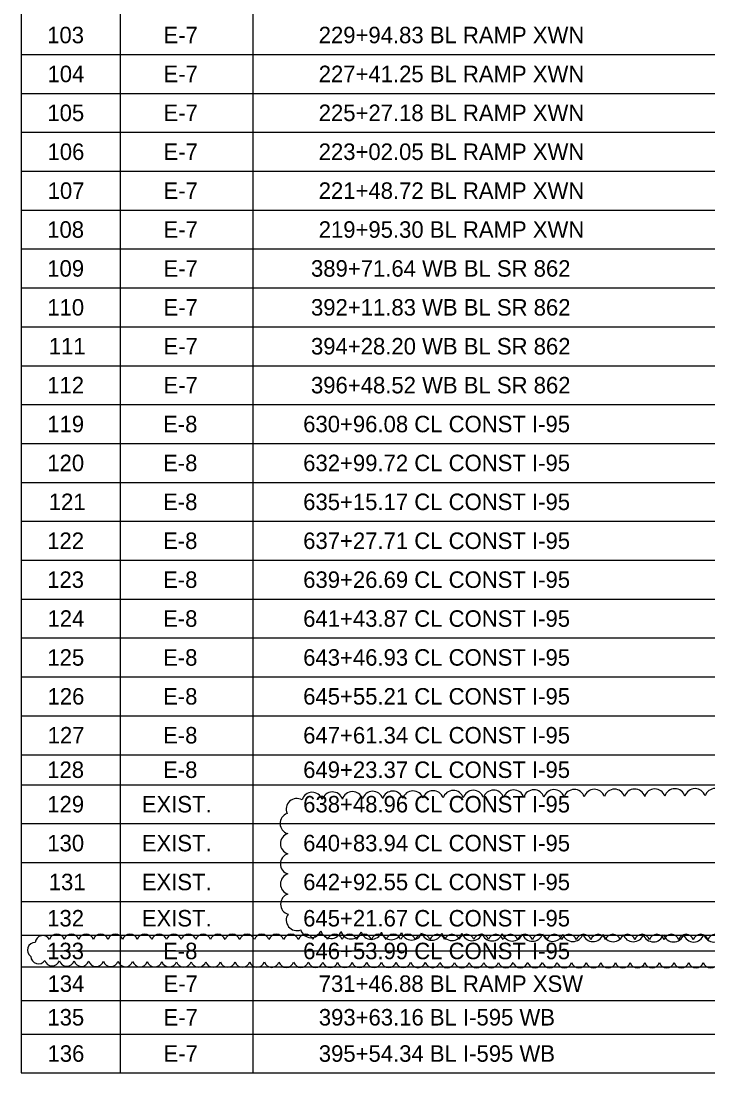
# Model space of a CAD drawing. Extents: x -818.1 to -802.4, y -2221.2 to -2187.7.
# Drawn here: x -817.208 to -814.295, y -2206.269 to -2201.807 of the extents above; entities that cross this region are included whole.
import ezdxf

# ---------------------------------------------------------------- set-up
doc = ezdxf.new("R2010")
doc.units = 0
for name, color, linetype in [('PlotBorder_dp', 7, 'Continuous'), ('SheetBorder_dp', 7, 'Continuous'), ('SheetLines_dp', 7, 'Continuous'), ('TextMinor', 7, 'Continuous'), ('TextTitle', 7, 'Continuous')]:
    doc.layers.add(name, color=color, linetype=linetype)

msp = doc.modelspace()

# ---------------------------------------------------------------- linework, layer by layer
at = {"layer": 'PlotBorder_dp'}
for p, q in [((-816.7882, -2199.8042), (-816.7882, -2206.2692)), ((-816.7882, -2199.8042), (-816.7882, -2206.2692)), ((-816.2257, -2199.8042), (-816.2257, -2206.2692)), ((-816.2257, -2199.8042), (-816.2257, -2206.2692))]:
    msp.add_line(p, q, dxfattribs=at)
at = {"layer": 'SheetLines_dp'}
for p, q in [((-817.2082, -2199.4742), (-817.2082, -2206.2692)), ((-817.2082, -2206.2692), (-811.1482, -2206.2692))]:
    msp.add_line(p, q, dxfattribs=at)
at = {"layer": 'TextMinor'}
for p, q in [((-817.2082, -2201.9492), (-809.6857, -2201.9492)), ((-817.2082, -2201.9492), (-809.6857, -2201.9492)), ((-817.2082, -2202.1142), (-809.6857, -2202.1142)), ((-817.2082, -2202.1142), (-809.6857, -2202.1142)), ((-817.2082, -2202.2792), (-809.6857, -2202.2792)), ((-817.2082, -2202.2792), (-809.6857, -2202.2792)), ((-817.2082, -2202.4442), (-809.6857, -2202.4442)), ((-817.2082, -2202.4442), (-809.6857, -2202.4442)), ((-817.2082, -2202.6092), (-809.6857, -2202.6092)), ((-817.2082, -2202.6092), (-809.6857, -2202.6092)), ((-817.2082, -2202.7742), (-809.6857, -2202.7742)), ((-817.2082, -2202.7742), (-809.6857, -2202.7742)), ((-817.2082, -2202.9392), (-809.6857, -2202.9392)), ((-817.2082, -2202.9392), (-809.6857, -2202.9392)), ((-817.2082, -2203.1042), (-809.6857, -2203.1042)), ((-817.2082, -2203.1042), (-809.6857, -2203.1042)), ((-817.2082, -2203.2692), (-809.6857, -2203.2692)), ((-817.2082, -2203.2692), (-809.6857, -2203.2692)), ((-817.2082, -2203.4342), (-809.6857, -2203.4342)), ((-817.2082, -2203.4342), (-809.6857, -2203.4342)), ((-817.2082, -2203.5992), (-809.6857, -2203.5992)), ((-817.2082, -2203.5992), (-809.6857, -2203.5992)), ((-817.2082, -2203.7642), (-809.6857, -2203.7642)), ((-817.2082, -2203.7642), (-809.6857, -2203.7642)), ((-817.2082, -2203.9292), (-809.6857, -2203.9292)), ((-817.2082, -2203.9292), (-809.6857, -2203.9292)), ((-817.2082, -2204.0942), (-809.6857, -2204.0942)), ((-817.2082, -2204.0942), (-809.6857, -2204.0942)), ((-817.2082, -2204.2592), (-809.6857, -2204.2592)), ((-817.2082, -2204.2592), (-809.6857, -2204.2592)), ((-817.2082, -2204.4242), (-809.6857, -2204.4242)), ((-817.2082, -2204.4242), (-809.6857, -2204.4242)), ((-817.2082, -2204.5892), (-809.6857, -2204.5892)), ((-817.2082, -2204.5892), (-809.6857, -2204.5892)), ((-817.2082, -2204.7542), (-809.6857, -2204.7542)), ((-817.2082, -2204.7542), (-809.6857, -2204.7542)), ((-817.2082, -2204.9192), (-816.7882, -2204.9192)), ((-817.2082, -2204.9192), (-809.6857, -2204.9192)), ((-816.2257, -2204.9192), (-809.6857, -2204.9192)), ((-817.2082, -2205.0467), (-809.6857, -2205.0467)), ((-817.2082, -2205.0467), (-809.6857, -2205.0467)), ((-817.2082, -2205.2117), (-816.2257, -2205.2117)), ((-817.2082, -2205.2117), (-809.6857, -2205.2117)), ((-817.2082, -2205.3767), (-813.6457, -2205.3767)), ((-817.2082, -2205.3767), (-809.6857, -2205.3767)), ((-817.2082, -2205.5417), (-816.7882, -2205.5417)), ((-817.2082, -2205.5417), (-809.6857, -2205.5417)), ((-817.2082, -2205.6842), (-816.2257, -2205.6842)), ((-817.2082, -2205.6842), (-809.6857, -2205.6842)), ((-817.2082, -2205.8192), (-809.6857, -2205.8192)), ((-816.7882, -2205.8192), (-811.1482, -2205.8192)), ((-817.2082, -2205.9617), (-816.7882, -2205.9617)), ((-817.2082, -2205.9617), (-809.6857, -2205.9617)), ((-816.2257, -2205.9617), (-814.2457, -2205.9617)), ((-817.2082, -2206.1042), (-809.6857, -2206.1042)), ((-816.7882, -2206.1042), (-816.2257, -2206.1042))]:
    msp.add_line(p, q, dxfattribs=at)
at = {"layer": 'TextTitle'}
msp.add_line((-817.0974, -2205.7517), (-809.7376, -2205.7517), dxfattribs=at)
for centre, radius, start, end in [((-815.9733, -2205.1234), 0.0448, 18.7303, 163.7303), ((-815.8879, -2205.1218), 0.0448, 18.4349, 163.4349), ((-815.8025, -2205.1205), 0.0448, 18.2937, 163.2937), ((-815.717, -2205.1194), 0.0448, 18.2063, 163.2063), ((-815.6315, -2205.1184), 0.0448, 18.1454, 163.1454), ((-815.5461, -2205.1175), 0.0448, 18.0999, 163.0999), ((-815.4606, -2205.1166), 0.0448, 18.0641, 163.0641), ((-815.3752, -2205.1158), 0.0448, 18.035, 163.035), ((-815.2897, -2205.115), 0.0448, 18.0108, 163.0108), ((-815.2042, -2205.1143), 0.0448, 17.9902, 162.9902), ((-815.1188, -2205.1135), 0.0448, 17.9724, 162.9724), ((-815.0333, -2205.1129), 0.0448, 17.9568, 162.9568), ((-814.9478, -2205.1122), 0.0448, 17.9431, 162.9431), ((-814.8623, -2205.1115), 0.0448, 17.9308, 162.9308), ((-814.7769, -2205.1109), 0.0448, 17.9197, 162.9197), ((-814.6914, -2205.1103), 0.0448, 17.9097, 162.9097), ((-814.6059, -2205.1097), 0.0448, 17.9005, 162.9005), ((-814.5205, -2205.1091), 0.0448, 17.8922, 162.8922), ((-814.435, -2205.1085), 0.0448, 17.8844, 162.8844), ((-814.3495, -2205.1079), 0.0448, 17.8773, 162.8773), ((-814.264, -2205.1074), 0.0448, 17.8707, 162.8707), ((-816.0387, -2205.1497), 0.0448, 59.9612, 204.9612), ((-816.0648, -2205.211), 0.0448, 108.8776, 253.8776), ((-816.0635, -2205.2967), 0.0448, 107.8667, 252.8667), ((-816.0632, -2205.3822), 0.0448, 107.5797, 252.5797), ((-816.0631, -2205.4677), 0.0448, 107.5929, 252.5929), ((-816.0627, -2205.5531), 0.0448, 107.8913, 252.8913), ((-816.0385, -2205.6205), 0.0448, 146.7173, 291.7173), ((-815.9786, -2205.6506), 0.0448, 194.8595, 339.8595), ((-815.8934, -2205.6539), 0.0448, 195.7789, 340.7789), ((-815.808, -2205.6561), 0.0448, 196.1857, 341.1857), ((-815.7226, -2205.6579), 0.0448, 196.4302, 341.4302), ((-815.6372, -2205.6594), 0.0448, 196.598, 341.598), ((-815.5517, -2205.6606), 0.0448, 196.7224, 341.7224), ((-815.4663, -2205.6617), 0.0448, 196.8195, 341.8195), ((-815.3809, -2205.6627), 0.0448, 196.8979, 341.8979), ((-815.2954, -2205.6635), 0.0448, 196.963, 341.963), ((-817.1482, -2205.7483), 0.0325, 89.8591, 234.8591), ((-817.1157, -2205.7187), 0.0325, 30.0061, 175.0061), ((-817.0566, -2205.7123), 0.0325, 17.2993, 162.2993), ((-816.9945, -2205.7125), 0.0325, 17.3718, 162.3718), ((-816.9324, -2205.7126), 0.0325, 17.4014, 162.4014), ((-816.8704, -2205.7127), 0.0325, 17.4187, 162.4187), ((-816.8083, -2205.7128), 0.0325, 17.4304, 162.4304), ((-816.7462, -2205.7128), 0.0325, 17.4391, 162.4391), ((-816.6842, -2205.7129), 0.0325, 17.4458, 162.4458), ((-816.6221, -2205.7129), 0.0325, 17.4511, 162.4511), ((-816.5601, -2205.713), 0.0325, 17.4556, 162.4556), ((-816.498, -2205.713), 0.0325, 17.4594, 162.4594), ((-816.4359, -2205.7131), 0.0325, 17.4626, 162.4626), ((-816.3739, -2205.7131), 0.0325, 17.4654, 162.4654), ((-816.3118, -2205.7132), 0.0325, 17.4679, 162.4679), ((-816.2498, -2205.7132), 0.0325, 17.4701, 162.4701), ((-816.1877, -2205.7132), 0.0325, 17.4721, 162.4721), ((-816.1257, -2205.7133), 0.0325, 17.4739, 162.4739), ((-816.0636, -2205.7133), 0.0325, 17.4756, 162.4756), ((-816.0015, -2205.7133), 0.0325, 17.4771, 162.4771), ((-815.9395, -2205.7133), 0.0325, 17.4784, 162.4784), ((-815.8774, -2205.7133), 0.0325, 17.4797, 162.4797), ((-815.8154, -2205.7134), 0.0325, 17.4809, 162.4809), ((-815.7533, -2205.7134), 0.0325, 17.482, 162.482), ((-815.6912, -2205.7134), 0.0325, 17.483, 162.483), ((-815.6292, -2205.7134), 0.0325, 17.484, 162.484), ((-815.5671, -2205.7134), 0.0325, 17.4849, 162.4849), ((-815.5051, -2205.7135), 0.0325, 17.4858, 162.4858), ((-815.443, -2205.7135), 0.0325, 17.4866, 162.4866), ((-815.3809, -2205.7135), 0.0325, 17.4873, 162.4873), ((-815.3189, -2205.7135), 0.0325, 17.488, 162.488), ((-815.2568, -2205.7135), 0.0325, 17.4887, 162.4887), ((-815.2099, -2205.6643), 0.0448, 197.0182, 342.0182), ((-815.1948, -2205.7135), 0.0325, 17.4894, 162.4894), ((-815.1245, -2205.665), 0.0448, 197.0657, 342.0657), ((-815.1327, -2205.7135), 0.0325, 17.49, 162.49), ((-815.0707, -2205.7135), 0.0325, 17.4906, 162.4906), ((-815.039, -2205.6656), 0.0448, 197.1072, 342.1072), ((-815.0086, -2205.7136), 0.0325, 17.4912, 162.4912), ((-814.9535, -2205.6662), 0.0448, 197.1439, 342.1439), ((-814.9465, -2205.7136), 0.0325, 17.4917, 162.4917), ((-814.8845, -2205.7136), 0.0325, 17.4922, 162.4922), ((-814.8681, -2205.6667), 0.0448, 197.1765, 342.1765), ((-814.8224, -2205.7136), 0.0325, 17.4927, 162.4927), ((-814.7826, -2205.6671), 0.0448, 197.2059, 342.2059), ((-814.7604, -2205.7136), 0.0325, 17.4932, 162.4932), ((-814.6971, -2205.6675), 0.0448, 197.2325, 342.2325), ((-814.6983, -2205.7136), 0.0325, 17.4936, 162.4936), ((-814.6362, -2205.7136), 0.0325, 17.4941, 162.4941), ((-814.6117, -2205.6679), 0.0448, 197.2567, 342.2567), ((-814.5742, -2205.7136), 0.0325, 17.4945, 162.4945), ((-814.5262, -2205.6683), 0.0448, 197.2789, 342.2789), ((-814.5121, -2205.7136), 0.0325, 17.4949, 162.4949), ((-814.4407, -2205.6686), 0.0448, 197.2994, 342.2994), ((-814.4501, -2205.7136), 0.0325, 17.4953, 162.4953), ((-814.388, -2205.7136), 0.0325, 17.4957, 162.4957), ((-814.3553, -2205.6689), 0.0448, 197.3182, 342.3182), ((-814.326, -2205.7136), 0.0325, 17.4961, 162.4961), ((-814.2698, -2205.6691), 0.0448, 197.3358, 342.3358), ((-814.2639, -2205.7136), 0.0325, 17.4964, 162.4964), ((-817.1344, -2205.774), 0.0326, 181.6179, 326.6179), ((-817.076, -2205.7828), 0.0325, 196.2837, 341.2837), ((-817.014, -2205.7839), 0.0325, 196.7139, 341.7139), ((-816.952, -2205.7846), 0.0325, 196.8932, 341.8932), ((-816.8899, -2205.7852), 0.0325, 196.9988, 341.9988), ((-816.8279, -2205.7857), 0.0325, 197.0706, 342.0706), ((-816.7658, -2205.7861), 0.0325, 197.1234, 342.1234), ((-816.7038, -2205.7865), 0.0325, 197.1645, 342.1645), ((-816.6417, -2205.7869), 0.0325, 197.1975, 342.1975), ((-816.5797, -2205.7872), 0.0325, 197.2249, 342.2249), ((-816.5176, -2205.7875), 0.0325, 197.2481, 342.2481), ((-816.4556, -2205.7877), 0.0325, 197.268, 342.268), ((-816.3935, -2205.788), 0.0325, 197.2853, 342.2853), ((-816.3315, -2205.7882), 0.0325, 197.3007, 342.3007), ((-816.2694, -2205.7884), 0.0325, 197.3143, 342.3143), ((-816.2074, -2205.7886), 0.0325, 197.3266, 342.3266), ((-816.1453, -2205.7888), 0.0325, 197.3377, 342.3377), ((-816.0832, -2205.789), 0.0325, 197.3478, 342.3478), ((-816.0212, -2205.7891), 0.0325, 197.357, 342.357), ((-815.9591, -2205.7893), 0.0325, 197.3655, 342.3655), ((-815.8971, -2205.7894), 0.0325, 197.3734, 342.3734), ((-815.835, -2205.7895), 0.0325, 197.3807, 342.3807), ((-815.773, -2205.7897), 0.0325, 197.3875, 342.3875), ((-815.7109, -2205.7898), 0.0325, 197.3938, 342.3938), ((-815.6488, -2205.7899), 0.0325, 197.3998, 342.3998), ((-815.5868, -2205.79), 0.0325, 197.4053, 342.4053), ((-815.5247, -2205.7901), 0.0325, 197.4106, 342.4106), ((-815.4627, -2205.7902), 0.0325, 197.4155, 342.4155), ((-815.4006, -2205.7903), 0.0325, 197.4202, 342.4202), ((-815.3386, -2205.7904), 0.0325, 197.4247, 342.4247), ((-815.2765, -2205.7905), 0.0325, 197.4289, 342.4289), ((-815.2144, -2205.7905), 0.0325, 197.4329, 342.4329), ((-815.1524, -2205.7906), 0.0325, 197.4368, 342.4368), ((-815.0903, -2205.7907), 0.0325, 197.4404, 342.4404), ((-815.0283, -2205.7907), 0.0325, 197.4439, 342.4439), ((-814.9662, -2205.7908), 0.0325, 197.4472, 342.4472), ((-814.9041, -2205.7908), 0.0325, 197.4504, 342.4504), ((-814.8421, -2205.7909), 0.0325, 197.4535, 342.4535), ((-814.78, -2205.7909), 0.0325, 197.4565, 342.4565), ((-814.718, -2205.791), 0.0325, 197.4593, 342.4593), ((-814.6559, -2205.791), 0.0325, 197.462, 342.462), ((-814.5939, -2205.7911), 0.0325, 197.4646, 342.4646), ((-814.5318, -2205.7911), 0.0325, 197.4672, 342.4672), ((-814.4697, -2205.7911), 0.0325, 197.4696, 342.4696), ((-814.4077, -2205.7912), 0.0325, 197.472, 342.472), ((-814.3456, -2205.7912), 0.0325, 197.4742, 342.4742), ((-814.2836, -2205.7912), 0.0325, 197.4765, 342.4765)]:
    msp.add_arc(centre, radius, start, end, dxfattribs=at)

# ---------------------------------------------------------------- texts
at = {"layer": 'SheetBorder_dp'}
for s, p in [('103', (-817.0974, -2201.9017)), ('E-7', (-816.6041, -2201.9017)), ('229+94.83 BL RAMP XWN', (-815.9458, -2201.9017)), ('104', (-817.096, -2202.0667)), ('E-7', (-816.6041, -2202.0667)), ('227+41.25 BL RAMP XWN', (-815.9458, -2202.0667)), ('105', (-817.0965, -2202.2317)), ('E-7', (-816.6041, -2202.2317)), ('225+27.18 BL RAMP XWN', (-815.9458, -2202.2317)), ('106', (-817.0959, -2202.3967)), ('E-7', (-816.6041, -2202.3967)), ('223+02.05 BL RAMP XWN', (-815.9458, -2202.3967)), ('107', (-817.0953, -2202.5617)), ('E-7', (-816.6041, -2202.5617)), ('221+48.72 BL RAMP XWN', (-815.9458, -2202.5617)), ('108', (-817.0971, -2202.7267)), ('E-7', (-816.6041, -2202.7267)), ('219+95.30 BL RAMP XWN', (-815.9458, -2202.7267)), ('109', (-817.097, -2202.8917)), ('389+71.64 WB BL SR 862', (-815.9785, -2202.8917)), ('E-7', (-816.6041, -2202.8917)), ('110', (-817.0968, -2203.0567)), ('E-7', (-816.6041, -2203.0567)), ('392+11.83 WB BL SR 862', (-815.9785, -2203.0567)), ('111', (-817.0906, -2203.2217)), ('E-7', (-816.6041, -2203.2217)), ('394+28.20 WB BL SR 862', (-815.9785, -2203.2217)), ('112', (-817.0973, -2203.3867)), ('E-7', (-816.6041, -2203.3867)), ('396+48.52 WB BL SR 862', (-815.9785, -2203.3867)), ('119', (-817.097, -2203.5517)), ('E-8', (-816.6058, -2203.5517)), ('630+96.08 CL CONST I-95', (-816.0115, -2203.5517)), ('120', (-817.0968, -2203.7167)), ('E-8', (-816.6058, -2203.7167)), ('632+99.72 CL CONST I-95', (-816.0115, -2203.7167)), ('121', (-817.0906, -2203.8817)), ('E-8', (-816.6058, -2203.8817)), ('635+15.17 CL CONST I-95', (-816.0115, -2203.8817)), ('122', (-817.0973, -2204.0467)), ('E-8', (-816.6058, -2204.0467)), ('637+27.71 CL CONST I-95', (-816.0115, -2204.0467)), ('123', (-817.0974, -2204.2117)), ('E-8', (-816.6058, -2204.2117)), ('639+26.69 CL CONST I-95', (-816.0115, -2204.2117)), ('124', (-817.096, -2204.3767)), ('E-8', (-816.6058, -2204.3767)), ('641+43.87 CL CONST I-95', (-816.0115, -2204.3767)), ('125', (-817.0965, -2204.5417)), ('E-8', (-816.6058, -2204.5417)), ('643+46.93 CL CONST I-95', (-816.0115, -2204.5417)), ('126', (-817.0959, -2204.7067)), ('E-8', (-816.6058, -2204.7067)), ('645+55.21 CL CONST I-95', (-816.0115, -2204.7067)), ('127', (-817.0953, -2204.8717)), ('E-8', (-816.6058, -2204.8717)), ('647+61.34 CL CONST I-95', (-816.0115, -2204.8717)), ('128', (-817.0971, -2205.0179)), ('E-8', (-816.6058, -2205.0179)), ('649+23.37 CL CONST I-95', (-816.0115, -2205.0179)), ('129', (-817.097, -2205.1642)), ('EXIST.', (-816.6962, -2205.1642)), ('638+48.96 CL CONST I-95', (-816.0115, -2205.1642)), ('130', (-817.0968, -2205.3292)), ('EXIST.', (-816.6962, -2205.3292)), ('640+83.94 CL CONST I-95', (-816.0115, -2205.3292)), ('131', (-817.0906, -2205.4942)), ('EXIST.', (-816.6962, -2205.4942)), ('642+92.55 CL CONST I-95', (-816.0115, -2205.4942)), ('132', (-817.0973, -2205.6479)), ('EXIST.', (-816.6962, -2205.6479)), ('645+21.67 CL CONST I-95', (-816.0115, -2205.6479)), ('133', (-817.0974, -2205.7867)), ('E-8', (-816.6058, -2205.7867)), ('646+53.99 CL CONST I-95', (-816.0115, -2205.7867)), ('134', (-817.096, -2205.9254)), ('731+46.88 BL RAMP XSW', (-815.9458, -2205.9254)), ('E-7', (-816.6041, -2205.9254)), ('135', (-817.0965, -2206.0679)), ('E-7', (-816.6041, -2206.0679)), ('393+63.16 BL I-595 WB', (-815.9453, -2206.0679)), ('136', (-817.0959, -2206.2217)), ('E-7', (-816.6041, -2206.2217)), ('395+54.34 BL I-595 WB', (-815.9453, -2206.2217))]:
    msp.add_text(s, height=0.07, dxfattribs=at).set_placement(p)

doc.saveas('drawing.dxf')
